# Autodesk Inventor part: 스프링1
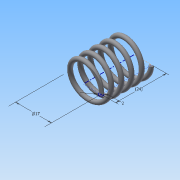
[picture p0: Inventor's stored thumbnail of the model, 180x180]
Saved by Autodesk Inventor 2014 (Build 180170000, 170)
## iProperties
Created: 2016-01
Part Number: 스프링1
Material: 강철, 탄소
Document SubType Name: Modeling
Designer: Administrator
Density: 7.87 g/cm^3
Appearance: 반연마
Mass: 6.47306 g
Surface Area: 16.7315 cm^2
Volume: 0.822499 cm^3
Author: Administrator
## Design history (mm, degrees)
sketch "스케치1"
  geometry: L1 (0, 0)-(8.5, 0); L2 (8.5, 0)-(8.5, 20.5); L3 (8.5, 20.5)-(0, 20.5); L4 (0, 20.5)-(0, 0); C1 r 1 at (8.5, 0)
  constraints: 8 end point, 2 parallel, 1 centre point, 1 coincident, 1 horizontal, 1 perpendicular
  dimensions: "d0" = 17 diameter of L2 L4; "d1" = 20.5 distance of L1.end L2.end (derived); "d2" = 2 diameter of C1
feature "코일1" sketch "스케치1" pitch "d3" = 10; turns "d5" = 5; dims "d4" = 20.5 (= d1), "d6" = 0, angle "d7" = 90 deg, angle "d8" = 90 deg, "d9" = 0, "d10" = 0
node "작업 평면2"
sketch "스케치2"
  geometry: L1 (-7.5, 0)-(-9.5, 0) reference; 1 further point
  constraints: 1 horizontal alignment
extrude "돌출1" cut sketch "스케치2" distance "d13" = 10; taper "d14" = 0 deg
node "작업 평면3"
sketch "스케치3"
  geometry: L1 (-9.5, 0)-(-7.5, 0) reference; 1 further point
  constraints: 1 horizontal alignment
extrude "돌출2" cut sketch "스케치3" distance "d16" = 10; taper "d17" = 0 deg
node "솔리드1"
node "절단 모서리 투영1"
node "절단 모서리 투영2"
other parameters: "d12" = 0, "d15" = 20.5 (= d1)
